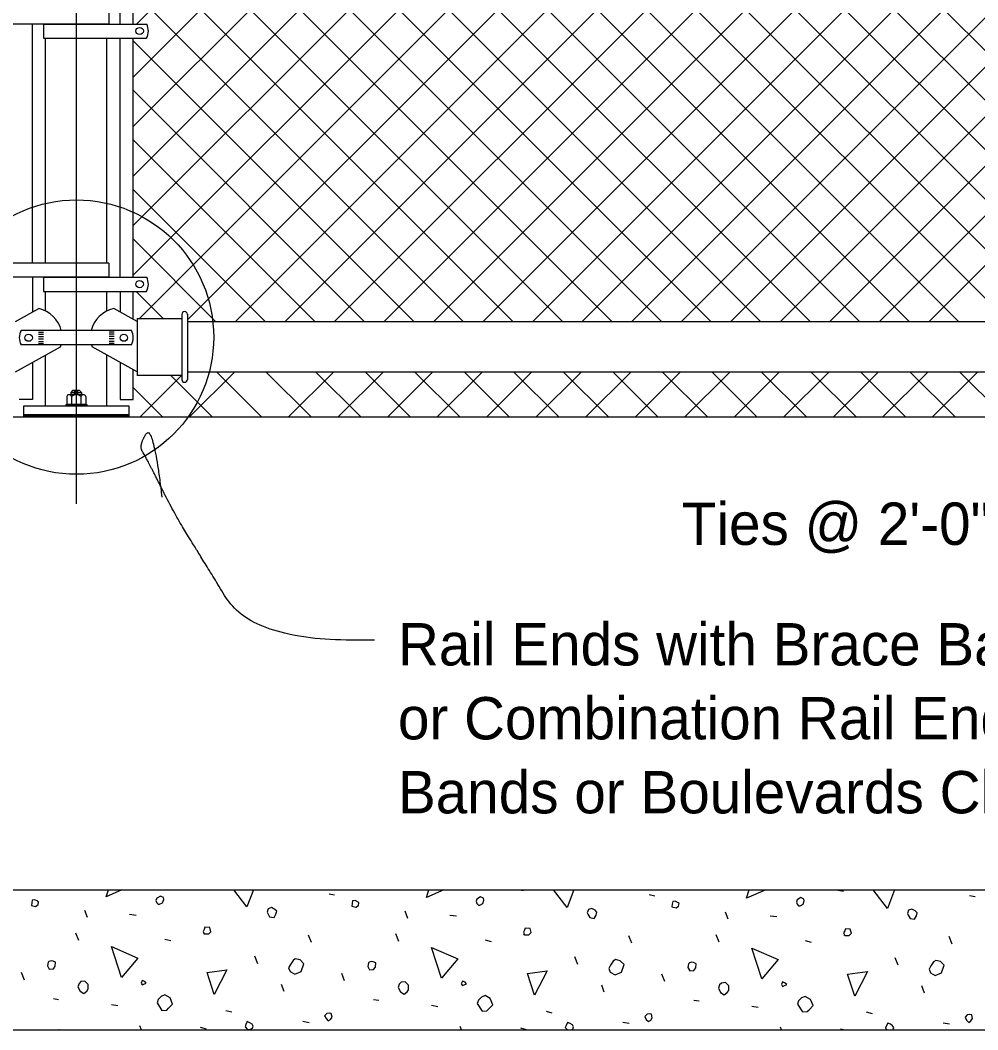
# Model space of a CAD drawing. Extents: x 0.4 to 38.5, y 1.2 to 25.4.
# Drawn here: x 11.808 to 16.365, y 14.041 to 18.845 of the extents above; entities that cross this region are included whole.
import ezdxf

# ---------------------------------------------------------------- set-up
doc = ezdxf.new("R2010")
doc.units = 0
for name, color, linetype in [('CL_Major', 7, 'Continuous'), ('Dimension', 7, 'Continuous'), ('Miscellaneous', 7, 'Continuous'), ('SteelMisc', 7, 'Continuous'), ('SupstrConc', 7, 'Continuous'), ('TextStructures', 7, 'Continuous')]:
    doc.layers.add(name, color=color, linetype=linetype)

msp = doc.modelspace()

# ---------------------------------------------------------------- linework, layer by layer
at = {"layer": 'CL_Major'}
msp.add_line((12.075, 24.4537), (12.075, 16.5436), dxfattribs=at)
at = {"layer": 'Dimension'}
msp.add_line((12.075, 17.0171), (12.075, 17.0164), dxfattribs=at)
msp.add_circle((12.0765, 17.337), 0.6527, dxfattribs=at)
msp.add_open_spline([(13.4943, 15.8955), (12.9219, 15.8776), (12.6525, 16.3184), (12.5475, 16.4863), (12.4086, 16.7637), (12.3723, 16.8197), (12.4405, 16.93), (12.4826, 16.5757)], degree=2, dxfattribs=at)
at = {"layer": 'Miscellaneous'}
for p, q in [((12.3459, 18.3388), (16.5946, 22.5875)), ((12.3459, 18.5745), (16.3589, 22.5875)), ((12.3622, 18.8265), (16.1232, 22.5875)), ((15.1887, 17.4104), (20.3658, 22.5875)), ((15.4244, 17.4104), (20.6015, 22.5875)), ((15.6601, 17.4104), (20.8372, 22.5875)), ((15.8958, 17.4104), (21.073, 22.5875)), ((16.1315, 17.4104), (21.3087, 22.5875)), ((12.5298, 22.5703), (17.6898, 17.4104)), ((12.7225, 22.1419), (17.4541, 17.4104)), ((12.3459, 22.0471), (16.9826, 17.4104)), ((12.5855, 22.0432), (17.2183, 17.4104)), ((12.3459, 21.8114), (16.7469, 17.4104)), ((12.3459, 21.5757), (16.5112, 17.4104)), ((12.3459, 21.34), (16.2755, 17.4104)), ((12.3459, 18.1031), (15.3576, 21.1148)), ((12.3459, 21.1043), (16.0398, 17.4104)), ((12.3459, 17.8674), (15.3576, 20.8791)), ((12.3459, 20.8686), (15.8041, 17.4104)), ((12.3459, 17.6317), (15.3576, 20.6434)), ((12.3459, 20.6329), (15.5684, 17.4104)), ((12.3757, 17.4258), (15.4595, 20.5096)), ((12.6044, 17.4187), (15.6952, 20.5096)), ((12.8317, 17.4104), (15.931, 20.5096)), ((13.0674, 17.4104), (16.1667, 20.5096)), ((13.3031, 17.4104), (16.4024, 20.5096)), ((13.5388, 17.4104), (16.6381, 20.5096)), ((13.7745, 17.4104), (16.8738, 20.5096)), ((14.0102, 17.4104), (17.1095, 20.5096)), ((14.2459, 17.4104), (17.3452, 20.5096)), ((14.4816, 17.4104), (17.5809, 20.5096)), ((14.7173, 17.4104), (17.8166, 20.5096)), ((14.953, 17.4104), (18.0523, 20.5096)), ((12.3459, 20.3972), (15.3327, 17.4104)), ((12.3459, 20.1615), (15.097, 17.4104)), ((12.3459, 19.9258), (14.8613, 17.4104)), ((12.3459, 19.6901), (14.6256, 17.4104)), ((12.3459, 19.4544), (14.3899, 17.4104)), ((12.3459, 19.2187), (14.1542, 17.4104)), ((12.3459, 18.983), (13.9185, 17.4104)), ((12.3459, 18.7473), (13.6828, 17.4104)), ((12.3459, 18.5116), (13.4471, 17.4104)), ((12.3459, 18.2759), (13.2114, 17.4104)), ((12.3459, 18.0402), (12.9757, 17.4104)), ((12.3459, 17.8045), (12.74, 17.4104)), ((12.3605, 17.5542), (12.4889, 17.4258)), ((12.3786, 16.9573), (12.5775, 17.1562)), ((12.5254, 17.1536), (12.7217, 16.9573)), ((12.6143, 16.9573), (12.8278, 17.1708)), ((12.7439, 17.1708), (12.9574, 16.9573)), ((12.9796, 17.1708), (13.1931, 16.9573)), ((13.0857, 16.9573), (13.2992, 17.1708)), ((13.2153, 17.1708), (13.4288, 16.9573)), ((13.3214, 16.9573), (13.5349, 17.1708)), ((13.451, 17.1708), (13.6645, 16.9573)), ((13.5571, 16.9573), (13.7706, 17.1708)), ((13.6867, 17.1708), (13.9002, 16.9573)), ((13.7928, 16.9573), (14.0063, 17.1708)), ((13.9224, 17.1708), (14.1359, 16.9573)), ((14.0285, 16.9573), (14.242, 17.1708)), ((14.1581, 17.1708), (14.3716, 16.9573)), ((14.2642, 16.9573), (14.4777, 17.1708)), ((14.3938, 17.1708), (14.6073, 16.9573)), ((14.4999, 16.9573), (14.7134, 17.1708)), ((14.6295, 17.1708), (14.843, 16.9573)), ((14.7356, 16.9573), (14.9491, 17.1708)), ((14.8652, 17.1708), (15.0787, 16.9573)), ((14.9713, 16.9573), (15.1848, 17.1708)), ((15.1009, 17.1708), (15.3144, 16.9573)), ((15.207, 16.9573), (15.4205, 17.1708)), ((15.3366, 17.1708), (15.5501, 16.9573)), ((15.4427, 16.9573), (15.6562, 17.1708)), ((15.5723, 17.1708), (15.7858, 16.9573)), ((15.6784, 16.9573), (15.8919, 17.1708)), ((15.808, 17.1708), (16.0215, 16.9573)), ((15.9141, 16.9573), (16.1276, 17.1708)), ((16.0437, 17.1708), (16.2573, 16.9573)), ((16.1498, 16.9573), (16.3633, 17.1708)), ((16.2794, 17.1708), (16.493, 16.9573)), ((12.0638, 17.0788), (12.0846, 17.0788)), ((12.0638, 17.0691), (12.0846, 17.0691)), ((12.3459, 17.0974), (12.486, 16.9573)), ((11.825, 16.9642), (12.325, 16.9642)), ((11.825, 16.9607), (12.325, 16.9607)), ((12.6778, 14.7072), (12.6789, 14.707)), ((14.1839, 14.7072), (14.2027, 14.7035)), ((15.7, 14.7053), (15.7265, 14.7)), ((13.2781, 14.6876), (13.3046, 14.6823)), ((14.8019, 14.684), (14.8285, 14.6787)), ((16.3258, 14.6805), (16.3523, 14.6752)), ((12.1291, 14.5744), (12.1167, 14.608)), ((12.3288, 14.5904), (12.3607, 14.5868)), ((13.6529, 14.5709), (13.6405, 14.6045)), ((13.8527, 14.5868), (13.8845, 14.5833)), ((15.1767, 14.5674), (15.1643, 14.601)), ((15.3765, 14.5833), (15.4083, 14.5797)), ((12.0867, 14.4648), (12.0725, 14.5002)), ((12.4968, 14.4719), (12.5251, 14.4648)), ((13.195, 14.456), (13.1809, 14.4914)), ((13.6105, 14.4613), (13.5963, 14.4967)), ((14.0206, 14.4684), (14.0489, 14.4613)), ((14.7189, 14.4525), (14.7047, 14.4878)), ((15.1343, 14.4578), (15.1201, 14.4931)), ((15.5444, 14.4648), (15.5727, 14.4578)), ((16.2427, 14.4489), (16.2285, 14.4843)), ((12.9387, 14.3552), (12.9246, 14.3906)), ((14.4625, 14.3517), (14.4484, 14.3871)), ((15.9863, 14.3482), (15.9722, 14.3835)), ((11.8286, 14.2775), (11.8144, 14.3128)), ((13.3524, 14.2739), (13.3382, 14.3093)), ((14.8762, 14.2704), (14.8621, 14.3057)), ((13.0642, 14.2227), (13.0519, 14.2562)), ((14.588, 14.2191), (14.5757, 14.2527)), ((16.1119, 14.2156), (16.0995, 14.2492)), ((11.9664, 14.1891), (11.9912, 14.1855)), ((13.4903, 14.1855), (13.515, 14.182)), ((15.0141, 14.182), (15.0388, 14.1785)), ((12.2422, 14.1608), (12.2723, 14.1555)), ((12.7867, 14.1325), (12.815, 14.1254)), ((13.766, 14.1572), (13.7961, 14.1519)), ((14.3105, 14.129), (14.3388, 14.1219)), ((15.2898, 14.1537), (15.3199, 14.1484)), ((15.8343, 14.1254), (15.8626, 14.1184)), ((13.1526, 14.0812), (13.1827, 14.0759)), ((14.6764, 14.0777), (14.7065, 14.0724)), ((12.3855, 14.0406), (12.3783, 14.06)), ((12.6647, 14.0529), (12.693, 14.0459)), ((13.908, 14.0406), (13.9022, 14.0565)), ((14.1885, 14.0494), (14.2168, 14.0423)), ((15.4305, 14.0406), (15.426, 14.0529)), ((15.7123, 14.0459), (15.7336, 14.0406)), ((16.2002, 14.0742), (16.2303, 14.0689))]:
    msp.add_line(p, q, dxfattribs=at)
msp.add_lwpolyline([(11.825, 16.9677), (12.325, 16.9677), (12.325, 16.9573), (11.825, 16.9573)], close=True, dxfattribs=at)
for points in [[(12.2175, 14.6734), (12.2279, 14.7072)], [(12.2927, 14.7072), (12.2175, 14.6734)], [(12.8875, 14.6257), (12.8255, 14.7072)], [(12.9179, 14.7072), (12.8875, 14.6257)], [(13.7413, 14.6699), (13.7528, 14.7072)], [(13.8244, 14.7072), (13.7413, 14.6699)], [(14.4113, 14.6222), (14.3466, 14.7072)], [(14.4431, 14.7072), (14.4113, 14.6222)], [(15.2651, 14.6664), (15.2777, 14.7072)], [(15.3561, 14.7072), (15.2651, 14.6664)], [(15.9351, 14.6186), (15.8677, 14.7072)], [(15.9682, 14.7072), (15.9351, 14.6186)], [(11.8621, 14.6328), (11.8816, 14.6275), (11.894, 14.6363), (11.8957, 14.6487), (11.8922, 14.6522), (11.8781, 14.6593), (11.8657, 14.6575), (11.8639, 14.6452), (11.8621, 14.6328)], [(12.465, 14.6381), (12.472, 14.6381), (12.4862, 14.6452), (12.4915, 14.6611), (12.4897, 14.6699), (12.4756, 14.677), (12.4579, 14.6664), (12.4544, 14.6558), (12.4579, 14.6452), (12.465, 14.6381)], [(13.386, 14.6292), (13.4054, 14.6239), (13.4178, 14.6328), (13.4196, 14.6452), (13.416, 14.6487), (13.4019, 14.6558), (13.3895, 14.654), (13.3877, 14.6416), (13.386, 14.6292)], [(13.9888, 14.6345), (13.9958, 14.6345), (14.01, 14.6416), (14.0153, 14.6575), (14.0135, 14.6664), (13.9994, 14.6734), (13.9817, 14.6628), (13.9782, 14.6522), (13.9817, 14.6416), (13.9888, 14.6345)], [(15.5126, 14.631), (15.5197, 14.631), (15.5338, 14.6381), (15.5391, 14.654), (15.5373, 14.6628), (15.5232, 14.6699), (15.5055, 14.6593), (15.502, 14.6487), (15.5055, 14.6381), (15.5126, 14.631)], [(12.9864, 14.5939), (12.9953, 14.578), (13.0165, 14.5744), (13.0253, 14.5904), (13.0289, 14.6045), (13.02, 14.6133), (13.0041, 14.6222), (12.9882, 14.6169), (12.9829, 14.601), (12.9864, 14.5939)], [(14.5103, 14.5904), (14.5191, 14.5744), (14.5403, 14.5709), (14.5492, 14.5868), (14.5527, 14.601), (14.5439, 14.6098), (14.5279, 14.6186), (14.512, 14.6133), (14.5067, 14.5974), (14.5103, 14.5904)], [(14.9098, 14.6257), (14.9292, 14.6204), (14.9416, 14.6292), (14.9434, 14.6416), (14.9398, 14.6452), (14.9257, 14.6522), (14.9133, 14.6505), (14.9115, 14.6381), (14.9098, 14.6257)], [(16.0341, 14.5868), (16.0429, 14.5709), (16.0641, 14.5674), (16.073, 14.5833), (16.0765, 14.5974), (16.0677, 14.6063), (16.0518, 14.6151), (16.0358, 14.6098), (16.0305, 14.5939), (16.0341, 14.5868)], [(12.6842, 14.4967), (12.7054, 14.4967), (12.716, 14.5073), (12.7107, 14.5267), (12.6877, 14.5285), (12.6842, 14.5179), (12.6789, 14.509), (12.6842, 14.4967), (12.6806, 14.5002)], [(14.208, 14.4931), (14.2292, 14.4931), (14.2398, 14.5037), (14.2345, 14.5232), (14.2115, 14.5249), (14.208, 14.5143), (14.2027, 14.5055), (14.208, 14.4931), (14.2044, 14.4967)], [(15.7318, 14.4896), (15.753, 14.4896), (15.7636, 14.5002), (15.7583, 14.5196), (15.7353, 14.5214), (15.7318, 14.5108), (15.7265, 14.502), (15.7318, 14.4896), (15.7283, 14.4931)], [(12.2899, 14.2898), (12.2422, 14.4366), (12.3677, 14.3818), (12.2899, 14.2898)], [(13.8138, 14.2863), (13.766, 14.433), (13.8915, 14.3782), (13.8138, 14.2863)], [(15.3376, 14.2828), (15.2898, 14.4295), (15.4154, 14.3747), (15.3376, 14.2828)], [(11.9382, 14.3446), (11.947, 14.3287), (11.9664, 14.3305), (11.9753, 14.3429), (11.9771, 14.3623), (11.9647, 14.3676), (11.9558, 14.3694), (11.9452, 14.3658), (11.9417, 14.3623), (11.9382, 14.3446)], [(13.0925, 14.3181), (13.1155, 14.3057), (13.1455, 14.3181), (13.1579, 14.3552), (13.1402, 14.3729), (13.1173, 14.3782), (13.1067, 14.3711), (13.0943, 14.3517), (13.0854, 14.3358), (13.0925, 14.3181)], [(13.462, 14.3411), (13.4708, 14.3252), (13.4903, 14.327), (13.4991, 14.3393), (13.5009, 14.3588), (13.4885, 14.3641), (13.4797, 14.3658), (13.469, 14.3623), (13.4655, 14.3588), (13.462, 14.3411)], [(14.6163, 14.3146), (14.6393, 14.3022), (14.6694, 14.3146), (14.6817, 14.3517), (14.6641, 14.3694), (14.6411, 14.3747), (14.6305, 14.3676), (14.6181, 14.3482), (14.6093, 14.3323), (14.6163, 14.3146)], [(16.1401, 14.311), (16.1631, 14.2987), (16.1932, 14.311), (16.2056, 14.3482), (16.1879, 14.3658), (16.1649, 14.3711), (16.1543, 14.3641), (16.1419, 14.3446), (16.1331, 14.3287), (16.1401, 14.311)], [(12.7319, 14.2085), (12.6983, 14.3128), (12.792, 14.3252), (12.7319, 14.2085)], [(14.2557, 14.205), (14.2221, 14.3093), (14.3158, 14.3216), (14.2557, 14.205)], [(14.9858, 14.3376), (14.9946, 14.3216), (15.0141, 14.3234), (15.0229, 14.3358), (15.0247, 14.3552), (15.0123, 14.3605), (15.0035, 14.3623), (14.9929, 14.3588), (14.9893, 14.3552), (14.9858, 14.3376)], [(15.7795, 14.2014), (15.7459, 14.3057), (15.8396, 14.3181), (15.7795, 14.2014)], [(12.0831, 14.2456), (12.0937, 14.2244), (12.1114, 14.2138), (12.1255, 14.2244), (12.1326, 14.235), (12.1326, 14.2562), (12.1167, 14.2722), (12.0973, 14.2704), (12.0884, 14.2615), (12.0831, 14.2456)], [(12.3889, 14.2545), (12.4084, 14.2633), (12.4013, 14.2704), (12.3889, 14.2757), (12.3836, 14.2633), (12.3889, 14.2545)], [(13.9128, 14.2509), (13.9322, 14.2598), (13.9251, 14.2668), (13.9128, 14.2722), (13.9075, 14.2598), (13.9128, 14.2509)], [(13.6069, 14.2421), (13.6175, 14.2209), (13.6352, 14.2103), (13.6494, 14.2209), (13.6564, 14.2315), (13.6564, 14.2527), (13.6405, 14.2686), (13.6211, 14.2668), (13.6122, 14.258), (13.6069, 14.2421)], [(15.1308, 14.2386), (15.1414, 14.2174), (15.159, 14.2067), (15.1732, 14.2174), (15.1802, 14.228), (15.1802, 14.2492), (15.1643, 14.2651), (15.1449, 14.2633), (15.1361, 14.2545), (15.1308, 14.2386)], [(15.4366, 14.2474), (15.456, 14.2562), (15.4489, 14.2633), (15.4366, 14.2686), (15.4313, 14.2562), (15.4366, 14.2474)], [(12.4597, 14.1696), (12.4826, 14.1325), (12.5056, 14.1343), (12.5145, 14.1431), (12.5339, 14.1626), (12.5215, 14.1926), (12.4968, 14.2067), (12.4791, 14.1997), (12.465, 14.1855), (12.4597, 14.1696)], [(13.9835, 14.1661), (14.0065, 14.129), (14.0294, 14.1307), (14.0383, 14.1396), (14.0577, 14.159), (14.0453, 14.1891), (14.0206, 14.2032), (14.0029, 14.1961), (13.9888, 14.182), (13.9835, 14.1661)], [(15.5073, 14.1626), (15.5303, 14.1254), (15.5532, 14.1272), (15.5621, 14.136), (15.5815, 14.1555), (15.5692, 14.1855), (15.5444, 14.1997), (15.5267, 14.1926), (15.5126, 14.1785), (15.5073, 14.1626)], [(12.8892, 14.0441), (12.9016, 14.0423), (12.914, 14.0476), (12.9175, 14.0583), (12.9122, 14.0671), (12.9016, 14.0742), (12.8892, 14.0795), (12.8822, 14.0653), (12.8786, 14.0547), (12.8892, 14.0441)], [(13.264, 14.0936), (13.2746, 14.083), (13.2852, 14.0901), (13.2923, 14.1007), (13.2887, 14.1184), (13.2799, 14.1201), (13.2675, 14.1184), (13.2569, 14.1077), (13.264, 14.0936)], [(14.7878, 14.0901), (14.7984, 14.0795), (14.809, 14.0865), (14.8161, 14.0971), (14.8126, 14.1148), (14.8037, 14.1166), (14.7913, 14.1148), (14.7807, 14.1042), (14.7878, 14.0901)], [(16.3116, 14.0865), (16.3222, 14.0759), (16.3328, 14.083), (16.3399, 14.0936), (16.3364, 14.1113), (16.3275, 14.1131), (16.3152, 14.1113), (16.3045, 14.1007), (16.3116, 14.0865)], [(11.9943, 14.0406), (11.993, 14.0423), (12.1927, 14.0406)], [(14.4295, 14.0406), (14.4378, 14.0441), (14.4413, 14.0547), (14.436, 14.0636), (14.4254, 14.0706), (14.413, 14.0759), (14.406, 14.0618), (14.4024, 14.0512), (14.413, 14.0406)], [(15.9616, 14.0406), (15.9651, 14.0512), (15.9598, 14.06), (15.9492, 14.0671), (15.9369, 14.0724), (15.9298, 14.0583), (15.9262, 14.0476), (15.9333, 14.0406)]]:
    msp.add_lwpolyline(points, dxfattribs=at)
at = {"layer": 'SteelMisc'}
for p, q in [((12.2834, 18.8265), (12.2834, 19.9637)), ((12.3459, 18.8265), (12.3459, 19.9637)), ((12.2309, 18.8942), (12.2309, 18.8265)), ((12.2309, 18.8265), (11.7405, 18.8265)), ((11.8667, 17.6895), (11.8667, 18.8265)), ((11.9193, 18.8265), (11.9193, 18.7589)), ((11.9193, 18.8265), (12.4104, 18.8265)), ((11.9193, 18.7589), (12.4096, 18.7589)), ((11.9292, 17.6895), (11.9292, 18.7589)), ((12.2209, 17.6895), (12.2209, 18.7589)), ((12.2834, 17.6219), (12.2834, 18.7589)), ((12.3459, 17.6219), (12.3459, 18.7589)), ((12.2309, 17.6895), (11.7397, 17.6895)), ((12.2309, 17.6895), (12.2309, 17.6219)), ((12.2309, 17.6219), (11.7405, 17.6219)), ((11.8667, 17.6219), (11.8667, 17.456)), ((11.9193, 17.6219), (11.9193, 17.5542)), ((11.9193, 17.6219), (12.4104, 17.6219)), ((11.9193, 17.5542), (12.4096, 17.5542)), ((11.9292, 17.4606), (11.9292, 17.5542)), ((12.2209, 17.4606), (12.2209, 17.5542)), ((12.2834, 17.5542), (12.2834, 17.456)), ((12.3459, 17.4214), (12.3459, 17.5542)), ((11.7855, 17.4111), (11.8963, 17.4724)), ((12.3646, 17.4111), (12.2537, 17.4724)), ((12.5775, 17.4454), (12.5775, 17.1357)), ((12.6044, 17.4454), (12.6044, 17.1357)), ((12.3646, 17.4258), (12.3646, 17.1536)), ((12.3646, 17.4258), (12.5775, 17.4258)), ((21.5457, 17.4104), (12.6044, 17.4104)), ((12.3374, 17.3685), (11.8126, 17.3685)), ((11.895, 17.3607), (11.9185, 17.3607)), ((11.895, 17.3511), (11.9185, 17.3511)), ((12.255, 17.3607), (12.2316, 17.3607)), ((12.255, 17.3511), (12.2316, 17.3511)), ((12.3374, 17.3007), (11.8126, 17.3007)), ((11.895, 17.3402), (11.9185, 17.3402)), ((11.895, 17.3285), (11.9185, 17.3285)), ((11.895, 17.3167), (11.9185, 17.3167)), ((11.895, 17.3069), (11.9185, 17.3069)), ((12.255, 17.3402), (12.2316, 17.3402)), ((12.255, 17.3285), (12.2316, 17.3285)), ((12.255, 17.3167), (12.2316, 17.3167)), ((12.255, 17.3069), (12.2316, 17.3069)), ((11.7855, 17.1717), (11.9994, 17.2902)), ((11.9292, 17.0093), (11.9292, 17.2513)), ((12.3646, 17.1717), (12.1506, 17.2902)), ((12.2209, 17.0093), (12.2209, 17.2513)), ((11.8667, 17.2167), (11.8667, 17.0406)), ((12.2834, 17.2167), (12.2834, 17.0406)), ((12.3459, 17.0406), (12.3459, 17.182)), ((12.5775, 17.1536), (12.3646, 17.1536)), ((21.5457, 17.1708), (12.6044, 17.1708)), ((12.1091, 17.0627), (12.0409, 17.0627)), ((12.0589, 17.0837), (12.0492, 17.074)), ((12.0492, 17.074), (12.0492, 17.0627)), ((12.0492, 17.074), (12.1007, 17.074)), ((12.0589, 17.0837), (12.0894, 17.0837)), ((12.0894, 17.0837), (12.1007, 17.074)), ((12.1007, 17.074), (12.1007, 17.0627)), ((11.8667, 17.0406), (11.8042, 17.0406)), ((12.0253, 17.0164), (12.0253, 17.0093)), ((12.0253, 17.0164), (12.1247, 17.0164)), ((12.0296, 17.054), (12.0296, 17.0164)), ((12.1204, 17.0164), (12.0296, 17.0164)), ((12.0523, 17.0543), (12.0523, 17.0164)), ((12.0977, 17.0543), (12.0977, 17.0164)), ((12.1204, 17.054), (12.1204, 17.0164)), ((12.1247, 17.0164), (12.1247, 17.0093)), ((12.2834, 17.0406), (12.3459, 17.0406)), ((11.9552, 16.9677), (12.1948, 16.9677))]:
    msp.add_line(p, q, dxfattribs=at)
msp.add_lwpolyline([(11.825, 17.0093), (12.325, 17.0093), (12.325, 16.9677), (11.825, 16.9677)], close=True, dxfattribs=at)
for centre, radius, start, end in [((12.5909, 17.4453), 0.0134, 0, 180), ((12.5909, 17.1355), 0.0134, 180, 0), ((12.041, 17.0509), 0.0118, 16.5986, 164.7005), ((12.075, 17.028), 0.0347, 49.2015, 130.7985), ((12.109, 17.051), 0.0118, 15.1506, 163.5042)]:
    msp.add_arc(centre, radius, start, end, dxfattribs=at)
for centre, major_axis in [((12.3767, 18.7937), (-0.0177, 0)), ((12.3767, 18.7937), (-0.0177, 0)), ((12.3767, 17.5891), (-0.0177, 0)), ((11.8485, 17.334), (0.0178, 0)), ((12.3016, 17.334), (-0.0178, 0))]:
    msp.add_ellipse(centre, major_axis=major_axis, ratio=0.957868, dxfattribs=at)
for centre, major_axis, start_param, end_param in [((12.3408, 18.7933), (0.0776, 0), 5.810211, 6.745158), ((12.3408, 18.7933), (0.0776, 0), 5.810211, 6.745158), ((12.3408, 17.5887), (0.0776, 0), 5.800651, 6.745353), ((11.8618, 17.3365), (0.146, 0), 0.231126, 1.331255), ((12.2882, 17.3365), (-0.146, 0), 4.95193, 6.05206), ((11.8818, 17.3345), (-0.0776, 0), 5.810211, 6.75616), ((12.2683, 17.3345), (0.0776, 0), 5.810211, 6.75616), ((11.8618, 17.3365), (0.146, 0), 5.947976, 6.024627), ((12.2882, 17.3365), (-0.146, 0), 0.258558, 0.335209)]:
    msp.add_ellipse(centre, major_axis=major_axis, ratio=0.957868, start_param=start_param, end_param=end_param, dxfattribs=at)
at = {"layer": 'SupstrConc'}
for p, q in [((5.5315, 16.9573), (18.6893, 16.9573)), ((0.6881, 14.7072), (23.462, 14.7072)), ((0.6881, 14.0406), (23.462, 14.0406))]:
    msp.add_line(p, q, dxfattribs=at)

# ---------------------------------------------------------------- texts
at = {"layer": 'Dimension'}
for s, p in [('Rail Ends with Brace Bands (shown)', (13.6059, 15.7745)), ('or Combination Rail Ends with Brace', (13.6059, 15.4225)), ('Bands or Boulevards Clamps (Typ.)', (13.6059, 15.0705))]:
    msp.add_text(s, height=0.2016, dxfattribs=at).set_placement(p)
at = {"layer": 'TextStructures'}
msp.add_text('Ties @ 2\'-0" Centers', height=0.2016, dxfattribs=at).set_placement((14.9569, 16.3481))

doc.saveas('drawing.dxf')
